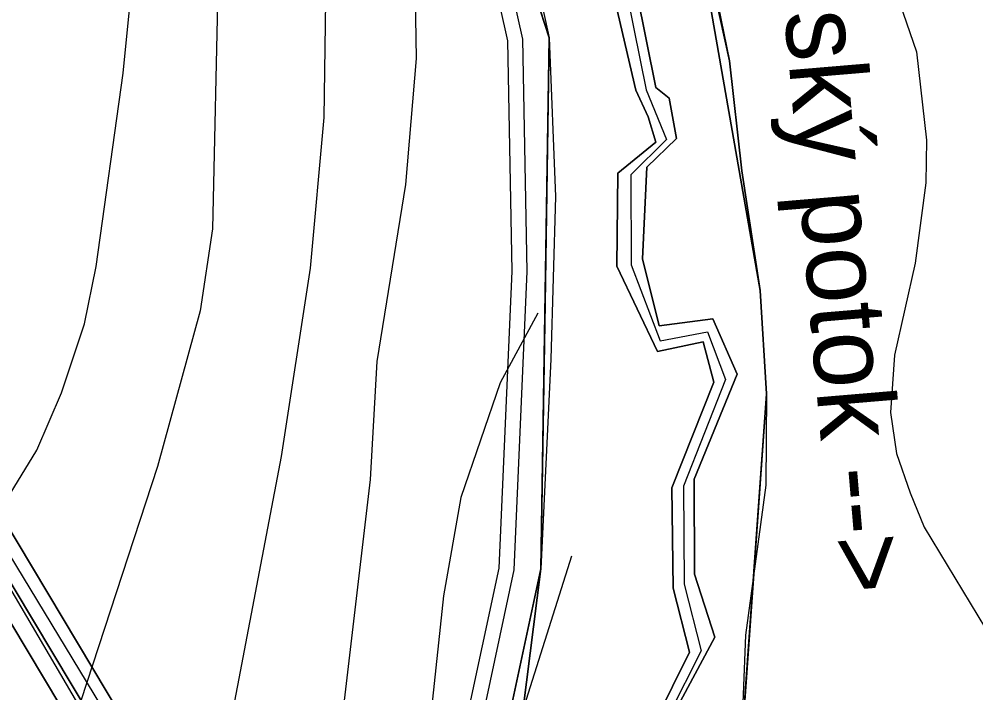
# Model space of a CAD drawing. Extents: x -1900516 to -575031, y -3809306 to -1157387.
# Drawn here: x -577857.8 to -577694.7, y -1160438.7 to -1160323.7 of the extents above; entities that cross this region are included whole.
import ezdxf

# ---------------------------------------------------------------- set-up
doc = ezdxf.new("R2010")
doc.units = 0
for name, color, linetype in [('01_PARCELY_NÁVRH_PC', 7, 'Continuous'), ('01_PARCELY_NÁVRH_ZPF', 7, 'Continuous'), ('01_PARCELY_NÁVRH_ŽP', 7, 'Continuous'), ('01_VRSTEVNICE', 7, 'Continuous'), ('02_KULTURY STAV', 7, 'Continuous'), ('03_PC_NÁVRH', 7, 'Continuous'), ('04_ZPF_OP_ORGAN', 7, 'Continuous'), ('04_ZPF_OP_TECH', 7, 'Continuous'), ('05_VHO_V_TOK', 7, 'Continuous'), ('06_CHR_ÚZEMÍ', 7, 'Continuous'), ('06_ÚSES_BK', 7, 'Continuous'), ('06_ÚSES_IP', 7, 'Continuous')]:
    doc.layers.add(name, color=color, linetype=linetype)

msp = doc.modelspace()

# ---------------------------------------------------------------- linework, layer by layer
at = {"layer": '01_PARCELY_NÁVRH_PC'}
for points in [[(-577745.19, -1160600.69), (-577762.82, -1160555.81), (-577774.38, -1160527.92), (-577776.27, -1160523.36), (-577779.15, -1160513.71), (-577781.75, -1160504.99), (-577782.67, -1160498.22), (-577782.71, -1160497.9), (-577784.46, -1160485.61), (-577784.28, -1160461.68), (-577781.64, -1160443.89), (-577775.96, -1160417.35), (-577773.73, -1160366.69), (-577774.51, -1160327.4), (-577778.3, -1160310.27), (-577797.73, -1160258.91), (-577805.81, -1160229.57), (-577808.52, -1160197.3), (-577805.56, -1160179.19), (-577801.67, -1160163.86)], [(-577794.72, -1160164.95), (-577798.88, -1160181.31), (-577801.64, -1160198.62), (-577798.83, -1160228.94), (-577791.25, -1160256.27), (-577779.4, -1160285.82), (-577771.37, -1160308.86), (-577767.45, -1160326.9), (-577766.37, -1160353.96), (-577767.15, -1160381.69), (-577768.84, -1160417.51), (-577774.66, -1160444.57), (-577777.28, -1160462), (-577777.46, -1160485.4), (-577774.79, -1160503.87), (-577771.44, -1160515.06), (-577771, -1160516.53), (-577769.73, -1160520.78), (-577764.23, -1160534.08), (-577761.96, -1160539.57), (-577756.2, -1160553.5), (-577746.81, -1160582.57)], [(-577901.44, -1160356.15), (-577828.27, -1160478.59), (-577795.98, -1160498.03), (-577785.15, -1160506.05), (-577779.15, -1160513.71), (-577781.75, -1160504.99), (-577782.67, -1160498.22), (-577786.65, -1160500.59), (-577794.03, -1160495.12), (-577825.71, -1160476.04), (-577898.12, -1160354.89)]]:
    msp.add_lwpolyline(points, dxfattribs=at)
at = {"layer": '01_PARCELY_NÁVRH_ZPF'}
msp.add_lwpolyline([(-578012, -1159885.55), (-578001.84, -1159934.51), (-577991.48, -1159989.82), (-577976.76, -1160052.71), (-577938.06, -1160229.78), (-577917.08, -1160329.69), (-577909.83, -1160359.68), (-577836.36, -1160484.85), (-577774.38, -1160527.92), (-577776.27, -1160523.36), (-577779.15, -1160513.71), (-577785.15, -1160506.05), (-577795.98, -1160498.03), (-577828.27, -1160478.59), (-577901.44, -1160356.15), (-577905.67, -1160333.62), (-577943.73, -1160152.15), (-577951.14, -1160115.39), (-577971.73, -1160026.05), (-577979.83, -1159987.31), (-577985.86, -1159963.03), (-577999.5, -1159891.38)], dxfattribs=at)
at = {"layer": '01_PARCELY_NÁVRH_ŽP'}
msp.add_lwpolyline([(-577996.08, -1159890.62), (-577982.44, -1159962.28), (-577976.42, -1159986.53), (-577968.31, -1160025.3), (-577947.72, -1160114.65), (-577940.3, -1160151.44), (-577902.24, -1160332.94), (-577898.12, -1160354.89), (-577825.71, -1160476.04), (-577794.03, -1160495.12), (-577786.65, -1160500.59), (-577782.67, -1160498.22), (-577791.52, -1160491.38), (-577822.42, -1160472.77), (-577893.85, -1160353.27), (-577897.83, -1160332.06), (-577935.89, -1160150.53), (-577943.32, -1160113.7), (-577963.91, -1160024.33), (-577972.03, -1159985.53), (-577978.04, -1159961.32), (-577991.69, -1159889.64)], dxfattribs=at)
at = {"layer": '01_VRSTEVNICE'}
for p, q in [((-577769.36, -1160373.86), (-577775.8, -1160385.75)), ((-577775.8, -1160385.75), (-577782.51, -1160405.32)), ((-577782.51, -1160405.32), (-577785.44, -1160422.1)), ((-577785.44, -1160422.1), (-577788.8, -1160453))]:
    msp.add_line(p, q, dxfattribs=at)
for points in [[(-578024.82, -1160574.79), (-578012.51, -1160563.18), (-577985.81, -1160533.68), (-577959.66, -1160510.61), (-577924.57, -1160481.39), (-577910.3, -1160468.24), (-577893.67, -1160451.61), (-577879.26, -1160434.41), (-577870.59, -1160422.94), (-577854.8, -1160397.22), (-577850.6, -1160387.43), (-577846.69, -1160375.68), (-577844.73, -1160365.9), (-577840.11, -1160332.9), (-577834.52, -1160276.97), (-577832.28, -1160234.46), (-577827.39, -1160190), (-577826.97, -1160169.87), (-577823.34, -1160132.95), (-577823.48, -1160114.5), (-577825.15, -1160100.79), (-577828.09, -1160087.09), (-577834.6, -1160064.58)], [(-577797.83, -1160116.18), (-577813.27, -1160170.43), (-577817.88, -1160197.27), (-577823.06, -1160262.15), (-577824.32, -1160297.94), (-577823.9, -1160315.84), (-577824.87, -1160359.46), (-577826.97, -1160373.45), (-577834.24, -1160400.01), (-577850.32, -1160449.23), (-577855.64, -1160460.97), (-577863.05, -1160473.98), (-577874.37, -1160489.36), (-577887.93, -1160504.6), (-577922.61, -1160538.43), (-577950.29, -1160563.74), (-577989.44, -1160601.77), (-578012.37, -1160622.33), (-578023.56, -1160630.58), (-578056.56, -1160650.99), (-578072.36, -1160661.76), (-578091.37, -1160677), (-578109.83, -1160694.89)], [(-577788.48, -1160146.64), (-577792.99, -1160155.6), (-577801.66, -1160177.98), (-577806.14, -1160192.72), (-577807.76, -1160199.61), (-577808.93, -1160210.42), (-577810.19, -1160231.95), (-577809.91, -1160259.35), (-577806.7, -1160291.23), (-577805.58, -1160320.59), (-577805.86, -1160340.45), (-577808.23, -1160366.18), (-577813.13, -1160398.33), (-577821.8, -1160443.64), (-577828.23, -1160467.13), (-577836.9, -1160488.94), (-577842.63, -1160498.59), (-577855.35, -1160515.78), (-577902.2, -1160572.41)], [(-577752.4, -1160191.88), (-577747.41, -1160197.27), (-577742.66, -1160205.24), (-577740, -1160212.65), (-577734.41, -1160240.06), (-577731.05, -1160257.67), (-577728.82, -1160273.33), (-577726.58, -1160280.6), (-577721.13, -1160294.03), (-577709.38, -1160315.84), (-577704.77, -1160329.26), (-577703.09, -1160344.36), (-577703.23, -1160351.63), (-577705.05, -1160365.34), (-577708.54, -1160381), (-577709.24, -1160390.78), (-577708.18, -1160397.83), (-577705.89, -1160404.49), (-577703.51, -1160410.36), (-577689.11, -1160434.13)], [(-577874.23, -1160588.21), (-577849.34, -1160557.73), (-577838.02, -1160541.65), (-577827.11, -1160522.91), (-577817.32, -1160502.92), (-577809.91, -1160482.79), (-577804.6, -1160459.3), (-577797.89, -1160402.25), (-577796.77, -1160382.11), (-577791.88, -1160351.91), (-577790.06, -1160330.38), (-577790.34, -1160313.04), (-577791.46, -1160296.27), (-577795.37, -1160269.42), (-577797.61, -1160245.93), (-577797.61, -1160232.51), (-577794.71, -1160221.42)], [(-578062.57, -1160980.83), (-578051.66, -1160955.38), (-578032.37, -1160918.19), (-578007.06, -1160875.12), (-577999.09, -1160859.46), (-577979.16, -1160806.52), (-577970.43, -1160788.43), (-577957.84, -1160766.62), (-577944.14, -1160746.49), (-577935.75, -1160735.3), (-577917.99, -1160714.33), (-577890.73, -1160687.34), (-577855.21, -1160656.44), (-577829.35, -1160631.7), (-577814.39, -1160613.94), (-577804.32, -1160596.32), (-577792.99, -1160570.87), (-577788.94, -1160559.69), (-577784.19, -1160539.83), (-577781.67, -1160518.02), (-577781.53, -1160489.64), (-577780.13, -1160475.52), (-577772.72, -1160444.2), (-577763.59, -1160415.28)]]:
    msp.add_lwpolyline(points, dxfattribs=at)
at = {"layer": '02_KULTURY STAV'}
for points in [[(-577695.34, -1160605.36), (-577731.52, -1160536.51), (-577747.07, -1160482.25), (-577734.73, -1160449.06), (-577730.37, -1160387.62), (-577731.48, -1160370), (-577747.88, -1160276.03), (-577756.15, -1160242.33), (-577752.66, -1160208.85), (-577751.07, -1160180.09), (-577762.75, -1160128.81), (-577779.67, -1160052.11), (-577784.89, -1160004.63), (-577794.79, -1159980.26), (-577801.46, -1159944.83), (-577841.89, -1159874.33)], [(-577841.89, -1159874.33), (-577801.46, -1159944.83), (-577794.79, -1159980.26), (-577784.89, -1160004.63), (-577779.67, -1160052.11), (-577762.75, -1160128.81), (-577751.07, -1160180.09), (-577752.66, -1160208.85), (-577756.15, -1160242.33), (-577747.88, -1160276.03), (-577731.48, -1160370), (-577730.37, -1160387.62), (-577734.73, -1160449.06), (-577747.07, -1160482.25), (-577731.52, -1160536.51), (-577695.34, -1160605.36)], [(-577867.61, -1159911.45), (-577829.25, -1160003.86), (-577822.89, -1160037.88), (-577828.93, -1160070.34), (-577795.51, -1160151.21), (-577798.83, -1160228.94), (-577767.45, -1160326.9), (-577768.84, -1160417.51), (-577777.46, -1160485.4), (-577731.24, -1160615.19), (-577667.64, -1160680.64), (-577647.35, -1160718.95), (-577652.9, -1160776.53), (-577680.98, -1160858.97), (-577702.23, -1160914.45), (-577728.27, -1160950.97), (-577751.28, -1160949.74), (-577757.88, -1160990.86)], [(-577757.88, -1160990.86), (-577751.28, -1160949.74), (-577728.27, -1160950.97), (-577702.23, -1160914.45), (-577680.98, -1160858.97), (-577652.9, -1160776.53), (-577647.35, -1160718.95), (-577667.64, -1160680.64), (-577731.24, -1160615.19), (-577777.46, -1160485.4), (-577768.84, -1160417.51), (-577767.45, -1160326.9), (-577798.83, -1160228.94), (-577795.51, -1160151.21), (-577828.93, -1160070.34), (-577822.89, -1160037.88), (-577829.25, -1160003.86), (-577867.61, -1159911.45)], [(-577726.41, -1160584.37), (-577733.56, -1160565.78), (-577744.03, -1160544.45), (-577745.8, -1160535.2), (-577749.81, -1160528.24), (-577753.9, -1160517.22), (-577758.87, -1160504.96), (-577762.78, -1160480.11), (-577758.42, -1160476.45), (-577758.72, -1160463.7), (-577755.11, -1160455.14), (-577743.54, -1160431.73), (-577746.31, -1160420.8), (-577746.5, -1160403.68), (-577739.34, -1160385.62), (-577741.2, -1160378.76), (-577748.99, -1160380.42), (-577755.93, -1160365.85), (-577755.71, -1160349.98), (-577749.24, -1160344.66), (-577750.57, -1160340.38), (-577752.66, -1160335.82), (-577756.48, -1160319.4)], [(-577756.48, -1160319.4), (-577752.66, -1160335.82), (-577750.57, -1160340.38), (-577749.24, -1160344.66), (-577755.71, -1160349.98), (-577755.93, -1160365.85), (-577748.99, -1160380.42), (-577741.2, -1160378.76), (-577739.34, -1160385.62), (-577746.5, -1160403.68), (-577746.31, -1160420.8), (-577743.54, -1160431.73), (-577755.11, -1160455.14), (-577758.72, -1160463.7), (-577758.42, -1160476.45), (-577762.78, -1160480.11), (-577758.87, -1160504.96), (-577753.9, -1160517.22), (-577749.81, -1160528.24), (-577745.8, -1160535.2), (-577744.03, -1160544.45), (-577733.56, -1160565.78), (-577726.41, -1160584.37)], [(-577752.47, -1160319.22), (-577749.24, -1160335.37), (-577747, -1160337.16), (-577745.72, -1160344.06), (-577750.8, -1160348.93), (-577751.53, -1160364.6), (-577748.69, -1160376.02), (-577739.56, -1160374.82), (-577735.38, -1160384.25), (-577742.71, -1160402.2), (-577742.64, -1160418.37), (-577739.2, -1160429.15), (-577751.35, -1160451.85), (-577755.15, -1160460.38), (-577754.97, -1160472.83), (-577758.15, -1160479.76), (-577756.49, -1160501.75), (-577751.35, -1160513.48), (-577747.49, -1160524.39), (-577740.55, -1160536.4), (-577739.46, -1160546.49), (-577729.26, -1160567), (-577720.18, -1160586.91)], [(-577720.18, -1160586.91), (-577729.26, -1160567), (-577739.46, -1160546.49), (-577740.55, -1160536.4), (-577747.49, -1160524.39), (-577751.35, -1160513.48), (-577756.49, -1160501.75), (-577758.15, -1160479.76), (-577754.97, -1160472.83), (-577755.15, -1160460.38), (-577751.35, -1160451.85), (-577739.2, -1160429.15), (-577742.64, -1160418.37), (-577742.71, -1160402.2), (-577735.38, -1160384.25), (-577739.56, -1160374.82), (-577748.69, -1160376.02), (-577751.53, -1160364.6), (-577750.8, -1160348.93), (-577745.72, -1160344.06), (-577747, -1160337.16), (-577749.24, -1160335.37), (-577752.47, -1160319.22)]]:
    msp.add_lwpolyline(points, dxfattribs=at)
at = {"layer": '03_PC_NÁVRH'}
msp.add_lwpolyline([(-577799.15, -1160164.09), (-577803.11, -1160179.7), (-577806, -1160197.4), (-577803.34, -1160229.13), (-577795.35, -1160258.13), (-577775.9, -1160309.55), (-577772.02, -1160327.1), (-577771.23, -1160366.72), (-577773.47, -1160417.67), (-577779.18, -1160444.33), (-577781.78, -1160461.87), (-577781.96, -1160485.44), (-577779.25, -1160504.5), (-577773.86, -1160522.57), (-577760.51, -1160554.85), (-577733.86, -1160617.17)], dxfattribs=at)
at = {"layer": '04_ZPF_OP_ORGAN'}
for points in [[(-577753.61, -1160163.02), (-577751.07, -1160180.09), (-577751.89, -1160206.99), (-577756.18, -1160229.28), (-577756, -1160243.7), (-577747.88, -1160276.03), (-577736.71, -1160330.82), (-577734.61, -1160349.58), (-577731.48, -1160370), (-577730.37, -1160387.62), (-577730.51, -1160403.21), (-577733.96, -1160428.79), (-577734.73, -1160449.06), (-577738.65, -1160463.57), (-577747.58, -1160481.82), (-577745.32, -1160491.56), (-577734.04, -1160521.51), (-577731.52, -1160536.51), (-577723.48, -1160557.34), (-577695.34, -1160605.36)], [(-577753.61, -1160163.02), (-577751.07, -1160180.09), (-577751.89, -1160206.99), (-577756.18, -1160229.28), (-577756, -1160243.7), (-577747.88, -1160276.03), (-577736.71, -1160330.82), (-577734.61, -1160349.58), (-577731.48, -1160370), (-577730.37, -1160387.62), (-577730.51, -1160403.21), (-577733.96, -1160428.79), (-577734.73, -1160449.06), (-577738.65, -1160463.57), (-577747.58, -1160481.82), (-577745.32, -1160491.56), (-577734.04, -1160521.51), (-577731.52, -1160536.51), (-577723.48, -1160557.34), (-577695.34, -1160605.36)], [(-577894.36, -1160361.27), (-577825.68, -1160478.41), (-577780.54, -1160508.91), (-577781.7, -1160505.04), (-577784.46, -1160485.61), (-577781.64, -1160443.88), (-577775.96, -1160417.35), (-577773.73, -1160366.69), (-577774.51, -1160327.4), (-577778.3, -1160310.27), (-577797.73, -1160258.91), (-577805.81, -1160229.57), (-577808.52, -1160197.3), (-577805.56, -1160179.19), (-577801.67, -1160163.86)], [(-577894.36, -1160361.27), (-577825.68, -1160478.41), (-577780.54, -1160508.91), (-577781.7, -1160505.04), (-577784.46, -1160485.61), (-577781.64, -1160443.88), (-577775.96, -1160417.35), (-577773.73, -1160366.69), (-577774.51, -1160327.4), (-577778.3, -1160310.27), (-577797.73, -1160258.91), (-577805.81, -1160229.57), (-577808.52, -1160197.3), (-577805.56, -1160179.19), (-577801.67, -1160163.86)]]:
    msp.add_lwpolyline(points, dxfattribs=at)
at = {"layer": '04_ZPF_OP_TECH'}
for points in [[(-577991.69, -1159889.64), (-577978.04, -1159961.32), (-577972.03, -1159985.53), (-577963.91, -1160024.33), (-577943.32, -1160113.7), (-577935.89, -1160150.53), (-577897.83, -1160332.06), (-577893.85, -1160353.27), (-577822.42, -1160472.77), (-577791.52, -1160491.38), (-577782.67, -1160498.22), (-577771, -1160516.53), (-577745.8, -1160535.2), (-577742.55, -1160547.47), (-577764.23, -1160534.08), (-577774.38, -1160527.92), (-577836.36, -1160484.85), (-577909.83, -1160359.68), (-577917.08, -1160329.69), (-577938.06, -1160229.78), (-577976.76, -1160052.71), (-577991.48, -1159989.82), (-578001.84, -1159934.51), (-578012, -1159885.55)], [(-577791.52, -1160491.38), (-577822.42, -1160472.77), (-577893.85, -1160353.27), (-577897.83, -1160332.06), (-577935.89, -1160150.53), (-577943.32, -1160113.7), (-577963.91, -1160024.33), (-577972.03, -1159985.53), (-577978.04, -1159961.32), (-577991.69, -1159889.64)]]:
    msp.add_lwpolyline(points, dxfattribs=at)
at = {"layer": '05_VHO_V_TOK'}
for p, q in [((-577754.11, -1160319.73), (-577750.89, -1160335.76)), ((-577750.89, -1160335.76), (-577747.45, -1160344.2)), ((-577747.45, -1160344.2), (-577753.51, -1160350.26)), ((-577753.51, -1160350.26), (-577753.48, -1160365.62)), ((-577753.48, -1160365.62), (-577748.52, -1160378.55)), ((-577748.52, -1160378.55), (-577740.43, -1160377.02)), ((-577740.43, -1160377.02), (-577737.37, -1160385.18)), ((-577737.37, -1160385.18), (-577744.55, -1160403.37)), ((-577744.55, -1160403.37), (-577744.42, -1160420.12)), ((-577744.42, -1160420.12), (-577741.54, -1160431.46)), ((-577741.54, -1160431.46), (-577757.47, -1160463.22))]:
    msp.add_line(p, q, dxfattribs=at)
at = {"layer": '06_CHR_ÚZEMÍ'}
for points in [[(-577867.61, -1159911.45), (-577829.25, -1160003.86), (-577822.89, -1160037.88), (-577828.93, -1160070.34), (-577795.51, -1160151.21), (-577798.83, -1160228.94), (-577767.45, -1160326.9), (-577768.14, -1160372.2), (-577768.84, -1160417.51), (-577774.66, -1160444.57), (-577777.28, -1160462), (-577777.46, -1160485.4), (-577774.79, -1160503.87), (-577769.73, -1160520.78), (-577757.03, -1160551.49), (-577741.14, -1160598.7)], [(-577667.93, -1160585.85), (-577690.79, -1160554.93), (-577724.02, -1160535.6), (-577736.19, -1160516.97), (-577740.78, -1160504.47), (-577747.07, -1160482.25), (-577740.9, -1160465.66), (-577734.73, -1160449.06), (-577732.55, -1160418.34), (-577730.37, -1160387.62), (-577731.48, -1160370), (-577734.61, -1160349.58), (-577736.71, -1160330.82), (-577743.19, -1160301.31), (-577747.88, -1160276.03), (-577752.02, -1160259.18), (-577755.99, -1160244.23), (-577756.18, -1160229.28), (-577751.89, -1160206.99), (-577751.07, -1160180.09), (-577753.61, -1160163.02)]]:
    msp.add_lwpolyline(points, dxfattribs=at)
at = {"layer": '06_ÚSES_BK'}
for p, q in [((-577767.45, -1160326.9), (-577798.83, -1160228.94)), ((-577743.19, -1160301.31), (-577736.71, -1160330.82)), ((-577768.14, -1160372.2), (-577767.45, -1160326.9)), ((-577731.48, -1160370), (-577730.37, -1160387.62)), ((-577768.84, -1160417.51), (-577768.14, -1160372.2)), ((-577730.37, -1160387.62), (-577732.55, -1160418.34)), ((-577732.55, -1160418.34), (-577734.73, -1160449.06))]:
    msp.add_line(p, q, dxfattribs=at)
for points in [[(-577736.71, -1160330.82), (-577734.61, -1160349.58), (-577731.48, -1160370)], [(-577777.46, -1160485.4), (-577776.98, -1160460.14), (-577774.66, -1160444.57), (-577768.84, -1160417.51)]]:
    msp.add_lwpolyline(points, dxfattribs=at)
at = {"layer": '06_ÚSES_IP'}
msp.add_lwpolyline([(-577782.67, -1160498.22), (-577822.26, -1160476.54), (-577894.45, -1160357.36), (-577943.45, -1160120.95), (-578007.84, -1159833.73), (-578013.92, -1159765.98), (-578034.43, -1159683.58), (-578046.29, -1159625), (-578065.74, -1159496.39)], dxfattribs=at)

# ---------------------------------------------------------------- texts
at = {"layer": '05_VHO_V_TOK'}
msp.add_text('Habrovanský potok -->', height=13, rotation=274.825, dxfattribs=at).set_placement((-577733.64, -1160247.44))

doc.saveas('drawing.dxf')
